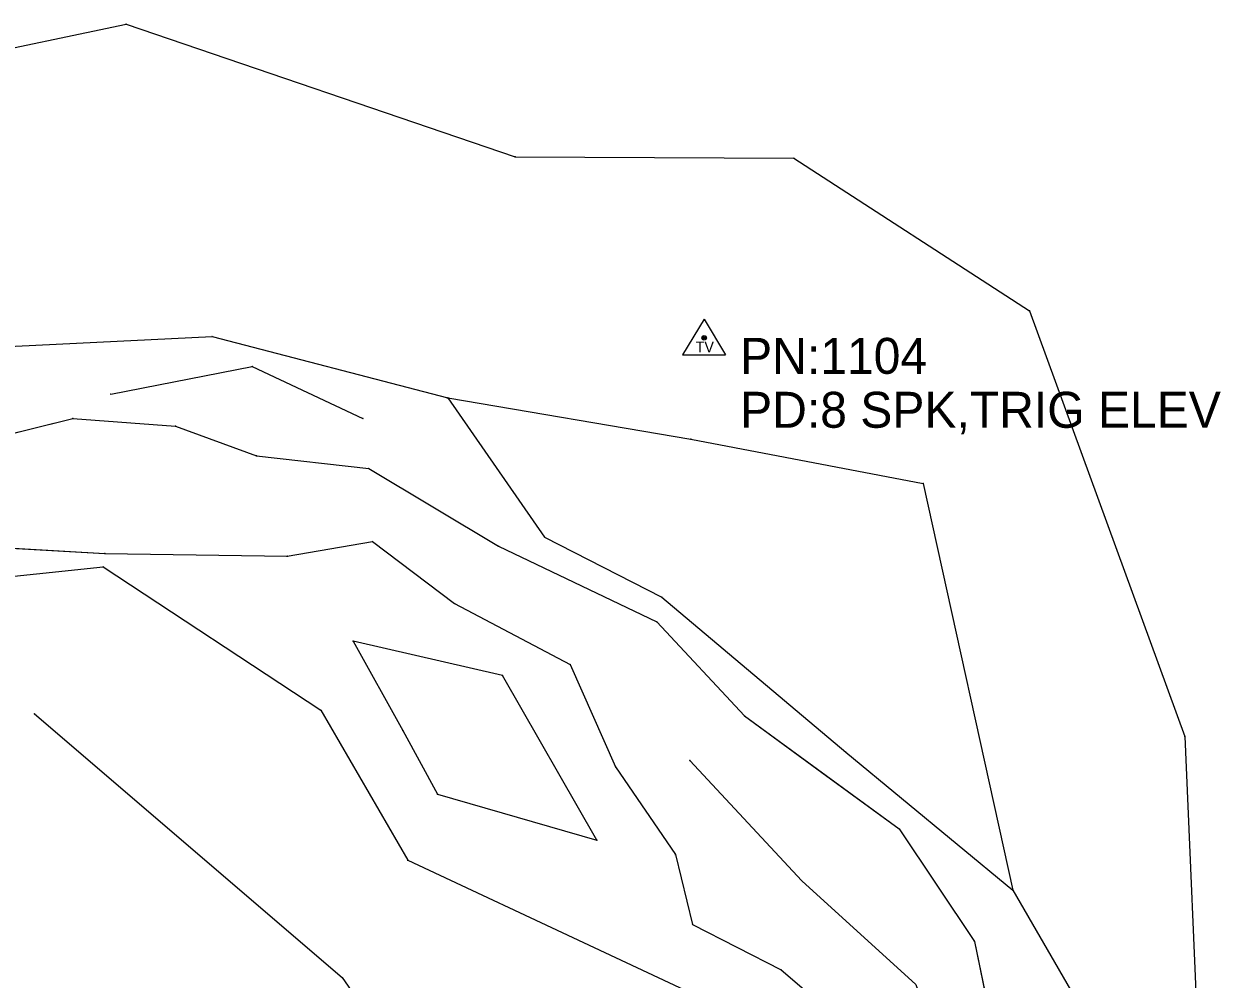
# Model space of a CAD drawing. Extents: x -99999 to 591807, y -99999 to 347168.
# Drawn here: x 588350.5 to 588517, y 345068.8 to 345201.6 of the extents above; entities that cross this region are included whole.
import ezdxf

# ---------------------------------------------------------------- set-up
doc = ezdxf.new("R2010")
doc.units = 0
for name, color, linetype in [('S_BREAKLINE', 7, 'Continuous'), ('S_DRG_PT_SYM', 7, 'Continuous'), ('S_GRD_PT_SYM', 7, 'Continuous'), ('S_SECONDARY_CTL', 7, 'Continuous'), ('S_SECONDARY_CTL_ANNOT', 7, 'Continuous'), ('S_STREAM', 7, 'Continuous')]:
    doc.layers.add(name, color=color, linetype=linetype)

msp = doc.modelspace()

# ---------------------------------------------------------------- linework, layer by layer
at = {"layer": 'S_BREAKLINE'}
for points in [[(588235.94, 344982.86), (588208.37, 345000.41), (588217.32, 345040.49), (588224.71, 345087.25), (588242.03, 345109.14), (588258.57, 345128.16), (588275.14, 345149.4), (588293.08, 345174.26), (588318.74, 345191.92), (588364.7, 345201.57), (588418.81, 345183.14), (588457.6, 345182.95), (588490.37, 345161.7), (588511.98, 345102.51), (588513.98, 345056.26), (588520.82, 345025.49), (588548.64, 345021.47), (588563.11, 345047.59), (588608.01, 345055.64)], [(588241.79, 344998.22), (588230.75, 345014.34), (588234.41, 345036.47), (588251.81, 345073.52), (588263.76, 345090.67), (588277.7, 345115.07), (588291.38, 345129.59), (588310.56, 345146.9), (588336.04, 345156.17), (588376.69, 345158.12), (588409.44, 345149.59), (588422.89, 345130.25), (588439.21, 345121.9), (588464.81, 345100.35), (588488.08, 345081.15), (588496.59, 345066.4), (588494.34, 345025.15), (588498.47, 345010.76), (588508.41, 345001.98), (588533.39, 344990.16), (588579.62, 344988.03), (588607.58, 345002.1)], [(588362.59, 345150.14), (588382.22, 345153.98), (588397.64, 345146.75)], [(588409.44, 345149.59), (588443.27, 345143.87), (588475.58, 345137.69)], [(588475.58, 345137.69), (588488.08, 345081.15)], [(588342.93, 345124.15), (588361.5, 345126.13), (588391.77, 345106.15), (588403.87, 345085.31), (588455.72, 345061.01), (588464.59, 345055.04), (588463.13, 345044.9), (588465.23, 345021.73), (588483.68, 344990.17), (588495.94, 344980.54), (588525.4, 344960.33), (588538.54, 344925.61), (588555.91, 344911.33), (588562.59, 344905.26), (588609.87, 344912.87), (588643.73, 344923.05), (588654.31, 344931.44), (588666.76, 344967), (588674.22, 344955.37), (588686.58, 344954.82), (588685.3, 344962.67), (588669.71, 344982.82), (588662.5, 344988.18), (588669.96, 344999.57)], [(588408.03, 345094.47), (588430.19, 345088.1), (588417.06, 345110.98), (588396.28, 345115.76), (588403.18, 345103.33), (588408.03, 345094.47)], [(588351.97, 345105.67), (588394.75, 345069), (588422.63, 345028.7), (588451.14, 344976.07), (588496.93, 344914.75), (588534.1, 344876.77), (588561.64, 344868.59), (588621.42, 344887.88), (588675.83, 344912.22), (588695.28, 344933.47)], [(588443.14, 345099.18), (588458.7, 345082.45), (588474.57, 345068.02), (588482.72, 345045), (588483.12, 345028.01), (588492.09, 345007.54)]]:
    msp.add_lwpolyline(points, dxfattribs=at)
at = {"layer": 'S_DRG_PT_SYM'}
for points in [[(588357.28, 345146.74), (588357.28, 345146.79), (588357.28, 345146.74), (588357.23, 345146.74), (588357.28, 345146.74), (588357.27, 345146.69), (588357.28, 345146.74), (588357.33, 345146.74)], [(588371.57, 345145.67), (588371.59, 345145.72), (588371.57, 345145.67), (588371.53, 345145.69), (588371.57, 345145.67), (588371.56, 345145.62), (588371.57, 345145.67), (588371.62, 345145.65)], [(588382.83, 345141.55), (588382.83, 345141.6), (588382.83, 345141.55), (588382.78, 345141.55), (588382.83, 345141.55), (588382.82, 345141.5), (588382.83, 345141.55), (588382.88, 345141.54)], [(588398.48, 345139.77), (588398.5, 345139.81), (588398.48, 345139.77), (588398.43, 345139.8), (588398.48, 345139.77), (588398.45, 345139.73), (588398.48, 345139.77), (588398.52, 345139.74)], [(588398.98, 345129.63), (588399.01, 345129.67), (588398.98, 345129.63), (588398.94, 345129.66), (588398.98, 345129.63), (588398.95, 345129.59), (588398.98, 345129.63), (588399.02, 345129.6)], [(588416.49, 345128.97), (588416.51, 345129.02), (588416.49, 345128.97), (588416.45, 345128.99), (588416.49, 345128.97), (588416.47, 345128.93), (588416.49, 345128.97), (588416.54, 345128.95)], [(588361.74, 345127.97), (588361.74, 345128.02), (588361.74, 345127.97), (588361.69, 345127.97), (588361.74, 345127.97), (588361.74, 345127.92), (588361.74, 345127.97), (588361.79, 345127.97)], [(588387.1, 345127.57), (588387.09, 345127.62), (588387.1, 345127.57), (588387.05, 345127.56), (588387.1, 345127.57), (588387.1, 345127.52), (588387.1, 345127.57), (588387.14, 345127.58)], [(588410.38, 345121), (588410.4, 345121.04), (588410.38, 345121), (588410.34, 345121.02), (588410.38, 345121), (588410.36, 345120.95), (588410.38, 345121), (588410.43, 345120.97)], [(588438.52, 345118.47), (588438.55, 345118.5), (588438.52, 345118.47), (588438.48, 345118.51), (588438.52, 345118.47), (588438.48, 345118.44), (588438.52, 345118.47), (588438.55, 345118.43)], [(588426.49, 345112.53), (588426.54, 345112.55), (588426.49, 345112.53), (588426.47, 345112.58), (588426.49, 345112.53), (588426.45, 345112.51), (588426.49, 345112.53), (588426.51, 345112.49)], [(588450.75, 345105.38), (588450.78, 345105.42), (588450.75, 345105.38), (588450.71, 345105.41), (588450.75, 345105.38), (588450.72, 345105.34), (588450.75, 345105.38), (588450.79, 345105.35)], [(588432.77, 345098.31), (588432.81, 345098.34), (588432.77, 345098.31), (588432.74, 345098.35), (588432.77, 345098.31), (588432.73, 345098.28), (588432.77, 345098.31), (588432.8, 345098.27)], [(588472.26, 345089.67), (588472.3, 345089.7), (588472.26, 345089.67), (588472.23, 345089.71), (588472.26, 345089.67), (588472.22, 345089.64), (588472.26, 345089.67), (588472.29, 345089.63)], [(588441.11, 345086.11), (588441.15, 345086.12), (588441.11, 345086.11), (588441.09, 345086.16), (588441.11, 345086.11), (588441.06, 345086.1), (588441.11, 345086.11), (588441.12, 345086.06)], [(588443.5, 345076.36), (588443.52, 345076.41), (588443.5, 345076.36), (588443.45, 345076.39), (588443.5, 345076.36), (588443.47, 345076.32), (588443.5, 345076.36), (588443.54, 345076.34)], [(588482.71, 345073.99), (588482.76, 345074), (588482.71, 345073.99), (588482.7, 345074.04), (588482.71, 345073.99), (588482.66, 345073.98), (588482.71, 345073.99), (588482.72, 345073.94)], [(588455.81, 345070.06), (588455.84, 345070.1), (588455.81, 345070.06), (588455.77, 345070.09), (588455.81, 345070.06), (588455.78, 345070.02), (588455.81, 345070.06), (588455.85, 345070.03)]]:
    msp.add_lwpolyline(points, close=True, dxfattribs=at)
at = {"layer": 'S_GRD_PT_SYM'}
for points in [[(588364.7, 345201.57), (588364.71, 345201.61), (588364.7, 345201.57), (588364.65, 345201.58), (588364.7, 345201.57), (588364.68, 345201.52), (588364.7, 345201.57), (588364.74, 345201.55)], [(588418.81, 345183.14), (588418.81, 345183.19), (588418.81, 345183.14), (588418.76, 345183.14), (588418.81, 345183.14), (588418.81, 345183.09), (588418.81, 345183.14), (588418.86, 345183.14)], [(588457.6, 345182.95), (588457.63, 345183), (588457.6, 345182.95), (588457.56, 345182.98), (588457.6, 345182.95), (588457.57, 345182.91), (588457.6, 345182.95), (588457.64, 345182.93)], [(588490.37, 345161.7), (588490.42, 345161.72), (588490.37, 345161.7), (588490.36, 345161.75), (588490.37, 345161.7), (588490.33, 345161.68), (588490.37, 345161.7), (588490.39, 345161.65)], [(588376.69, 345158.12), (588376.7, 345158.17), (588376.69, 345158.12), (588376.64, 345158.13), (588376.69, 345158.12), (588376.67, 345158.07), (588376.69, 345158.12), (588376.73, 345158.1)], [(588382.22, 345153.98), (588382.25, 345154.03), (588382.22, 345153.98), (588382.18, 345154), (588382.22, 345153.98), (588382.2, 345153.94), (588382.22, 345153.98), (588382.27, 345153.96)], [(588362.59, 345150.14), (588362.58, 345150.19), (588362.59, 345150.14), (588362.54, 345150.13), (588362.59, 345150.14), (588362.6, 345150.09), (588362.59, 345150.14), (588362.64, 345150.15)], [(588409.44, 345149.59), (588409.45, 345149.64), (588409.44, 345149.59), (588409.39, 345149.6), (588409.44, 345149.59), (588409.43, 345149.54), (588409.44, 345149.59), (588409.49, 345149.58)], [(588409.44, 345149.59), (588409.48, 345149.62), (588409.44, 345149.59), (588409.41, 345149.63), (588409.44, 345149.59), (588409.4, 345149.56), (588409.44, 345149.59), (588409.47, 345149.55)], [(588397.64, 345146.75), (588397.66, 345146.8), (588397.64, 345146.75), (588397.59, 345146.78), (588397.64, 345146.75), (588397.61, 345146.71), (588397.64, 345146.75), (588397.68, 345146.73)], [(588443.27, 345143.87), (588443.28, 345143.92), (588443.27, 345143.87), (588443.22, 345143.88), (588443.27, 345143.87), (588443.26, 345143.82), (588443.27, 345143.87), (588443.32, 345143.86)], [(588475.58, 345137.69), (588475.59, 345137.74), (588475.58, 345137.69), (588475.53, 345137.7), (588475.58, 345137.69), (588475.57, 345137.64), (588475.58, 345137.69), (588475.63, 345137.68)], [(588475.58, 345137.69), (588475.63, 345137.7), (588475.58, 345137.69), (588475.57, 345137.74), (588475.58, 345137.69), (588475.53, 345137.68), (588475.58, 345137.69), (588475.59, 345137.64)], [(588422.89, 345130.25), (588422.91, 345130.3), (588422.89, 345130.25), (588422.84, 345130.28), (588422.89, 345130.25), (588422.86, 345130.21), (588422.89, 345130.25), (588422.93, 345130.23)], [(588361.5, 345126.13), (588361.53, 345126.17), (588361.5, 345126.13), (588361.46, 345126.15), (588361.5, 345126.13), (588361.48, 345126.09), (588361.5, 345126.13), (588361.55, 345126.1)], [(588439.21, 345121.9), (588439.24, 345121.93), (588439.21, 345121.9), (588439.17, 345121.93), (588439.21, 345121.9), (588439.18, 345121.86), (588439.21, 345121.9), (588439.25, 345121.86)], [(588396.28, 345115.76), (588396.28, 345115.81), (588396.28, 345115.76), (588396.23, 345115.76), (588396.28, 345115.76), (588396.28, 345115.71), (588396.28, 345115.76), (588396.33, 345115.76)], [(588396.28, 345115.76), (588396.32, 345115.78), (588396.28, 345115.76), (588396.25, 345115.8), (588396.28, 345115.76), (588396.23, 345115.74), (588396.28, 345115.76), (588396.3, 345115.72)], [(588417.06, 345110.98), (588417.06, 345111.03), (588417.06, 345110.98), (588417.01, 345110.98), (588417.06, 345110.98), (588417.06, 345110.93), (588417.06, 345110.98), (588417.11, 345110.98)], [(588417.06, 345110.98), (588417.05, 345110.93), (588417.06, 345110.98), (588417.11, 345110.97), (588417.06, 345110.98), (588417.07, 345111.03), (588417.06, 345110.98), (588417.01, 345110.99)], [(588351.97, 345105.67), (588352, 345105.71), (588351.97, 345105.67), (588351.93, 345105.7), (588351.97, 345105.67), (588351.93, 345105.63), (588351.97, 345105.67), (588352, 345105.64)], [(588391.77, 345106.15), (588391.81, 345106.18), (588391.77, 345106.15), (588391.75, 345106.2), (588391.77, 345106.15), (588391.73, 345106.13), (588391.77, 345106.15), (588391.8, 345106.11)], [(588403.18, 345103.33), (588403.18, 345103.38), (588403.18, 345103.33), (588403.13, 345103.33), (588403.18, 345103.33), (588403.18, 345103.28), (588403.18, 345103.33), (588403.23, 345103.33)], [(588403.18, 345103.33), (588403.22, 345103.36), (588403.18, 345103.33), (588403.16, 345103.38), (588403.18, 345103.33), (588403.14, 345103.31), (588403.18, 345103.33), (588403.2, 345103.29)], [(588511.98, 345102.51), (588512.03, 345102.51), (588511.98, 345102.51), (588511.98, 345102.56), (588511.98, 345102.51), (588511.93, 345102.5), (588511.98, 345102.51), (588511.99, 345102.46)], [(588464.81, 345100.35), (588464.85, 345100.39), (588464.81, 345100.35), (588464.78, 345100.38), (588464.81, 345100.35), (588464.78, 345100.31), (588464.81, 345100.35), (588464.85, 345100.32)], [(588443.14, 345099.18), (588443.18, 345099.22), (588443.14, 345099.18), (588443.11, 345099.22), (588443.14, 345099.18), (588443.1, 345099.15), (588443.14, 345099.18), (588443.17, 345099.15)], [(588408.03, 345094.47), (588408.03, 345094.52), (588408.03, 345094.47), (588407.98, 345094.47), (588408.03, 345094.47), (588408.03, 345094.42), (588408.03, 345094.47), (588408.08, 345094.47)], [(588408.03, 345094.47), (588408.04, 345094.51), (588408.03, 345094.47), (588407.98, 345094.48), (588408.03, 345094.47), (588408.01, 345094.42), (588408.03, 345094.47), (588408.08, 345094.45)], [(588408.03, 345094.47), (588408.07, 345094.49), (588408.03, 345094.47), (588408, 345094.51), (588408.03, 345094.47), (588407.98, 345094.44), (588408.03, 345094.47), (588408.05, 345094.42)], [(588430.19, 345088.1), (588430.19, 345088.15), (588430.19, 345088.1), (588430.14, 345088.1), (588430.19, 345088.1), (588430.19, 345088.05), (588430.19, 345088.1), (588430.24, 345088.1)], [(588430.19, 345088.1), (588430.15, 345088.08), (588430.19, 345088.1), (588430.22, 345088.06), (588430.19, 345088.1), (588430.24, 345088.13), (588430.19, 345088.1), (588430.17, 345088.15)], [(588403.87, 345085.31), (588403.89, 345085.35), (588403.87, 345085.31), (588403.82, 345085.33), (588403.87, 345085.31), (588403.84, 345085.26), (588403.87, 345085.31), (588403.91, 345085.29)], [(588458.7, 345082.45), (588458.74, 345082.49), (588458.7, 345082.45), (588458.67, 345082.48), (588458.7, 345082.45), (588458.67, 345082.41), (588458.7, 345082.45), (588458.74, 345082.41)], [(588488.08, 345081.15), (588488.13, 345081.16), (588488.08, 345081.15), (588488.07, 345081.19), (588488.08, 345081.15), (588488.03, 345081.13), (588488.08, 345081.15), (588488.09, 345081.1)], [(588488.08, 345081.15), (588488.12, 345081.17), (588488.08, 345081.15), (588488.06, 345081.19), (588488.08, 345081.15), (588488.04, 345081.12), (588488.08, 345081.15), (588488.11, 345081.1)], [(588394.75, 345069), (588394.79, 345069.03), (588394.75, 345069), (588394.72, 345069.04), (588394.75, 345069), (588394.7, 345068.97), (588394.75, 345069), (588394.77, 345068.96)]]:
    msp.add_lwpolyline(points, close=True, dxfattribs=at)
at = {"layer": 'S_SECONDARY_CTL'}
for p, q in [((588445.12, 345160.56), (588442.11, 345155.61)), ((588445.12, 345160.56), (588448.07, 345155.61)), ((588442.11, 345155.61), (588448.07, 345155.61))]:
    msp.add_line(p, q, dxfattribs=at)
for radius in [0.311, 0.183, 0.103]:
    msp.add_circle((588445.12, 345157.95), radius, dxfattribs=at)
at = {"layer": 'S_STREAM'}
for points in [[(588317.56, 345136.92), (588357.28, 345146.74), (588371.57, 345145.67), (588382.83, 345141.55), (588398.48, 345139.77), (588416.49, 345128.97), (588438.52, 345118.47), (588450.75, 345105.38), (588472.26, 345089.67), (588482.71, 345073.99), (588489.64, 345040.56)], [(588337.42, 345141.83), (588357.28, 345146.74), (588371.57, 345145.67), (588382.83, 345141.55), (588398.48, 345139.77), (588416.49, 345128.97), (588438.52, 345118.47), (588450.75, 345105.38), (588461.5, 345097.52), (588472.26, 345089.67), (588482.71, 345073.99), (588486.18, 345057.27)], [(588336.3, 345129.42), (588361.74, 345127.97), (588387.1, 345127.57), (588398.98, 345129.63), (588410.38, 345121), (588426.49, 345112.53), (588432.77, 345098.31), (588441.11, 345086.11), (588443.5, 345076.36), (588455.81, 345070.06), (588467.81, 345059.79), (588473.73, 345052.15), (588474.83, 345047.75), (588471.91, 345040.97), (588475.57, 345025.49), (588488.57, 345005.12), (588498.65, 344989.67), (588531.26, 344973.41), (588535.88, 344960.6)], [(588349.02, 345128.7), (588361.74, 345127.97), (588374.42, 345127.77), (588387.1, 345127.57), (588398.98, 345129.63), (588410.38, 345121), (588426.49, 345112.53), (588432.77, 345098.31), (588441.11, 345086.11), (588443.5, 345076.36), (588455.81, 345070.06), (588467.81, 345059.79), (588473.73, 345052.15), (588474.83, 345047.75), (588471.91, 345040.97), (588475.57, 345025.49), (588488.57, 345005.12), (588498.65, 344989.67), (588514.95, 344981.54), (588531.26, 344973.41), (588535.88, 344960.6)]]:
    msp.add_lwpolyline(points, dxfattribs=at)

# ---------------------------------------------------------------- texts
at = {"layer": 'S_SECONDARY_CTL'}
msp.add_text('TV', height=1.5, rotation=360, dxfattribs=at).set_placement((588443.92, 345155.94))
at = {"layer": 'S_SECONDARY_CTL_ANNOT'}
for s, p in [('PN:1104', (588450.12, 345152.95)), ('PD:8 SPK,TRIG ELEV', (588450.12, 345145.45))]:
    msp.add_text(s, height=5, dxfattribs=at).set_placement(p)

doc.saveas('drawing.dxf')
